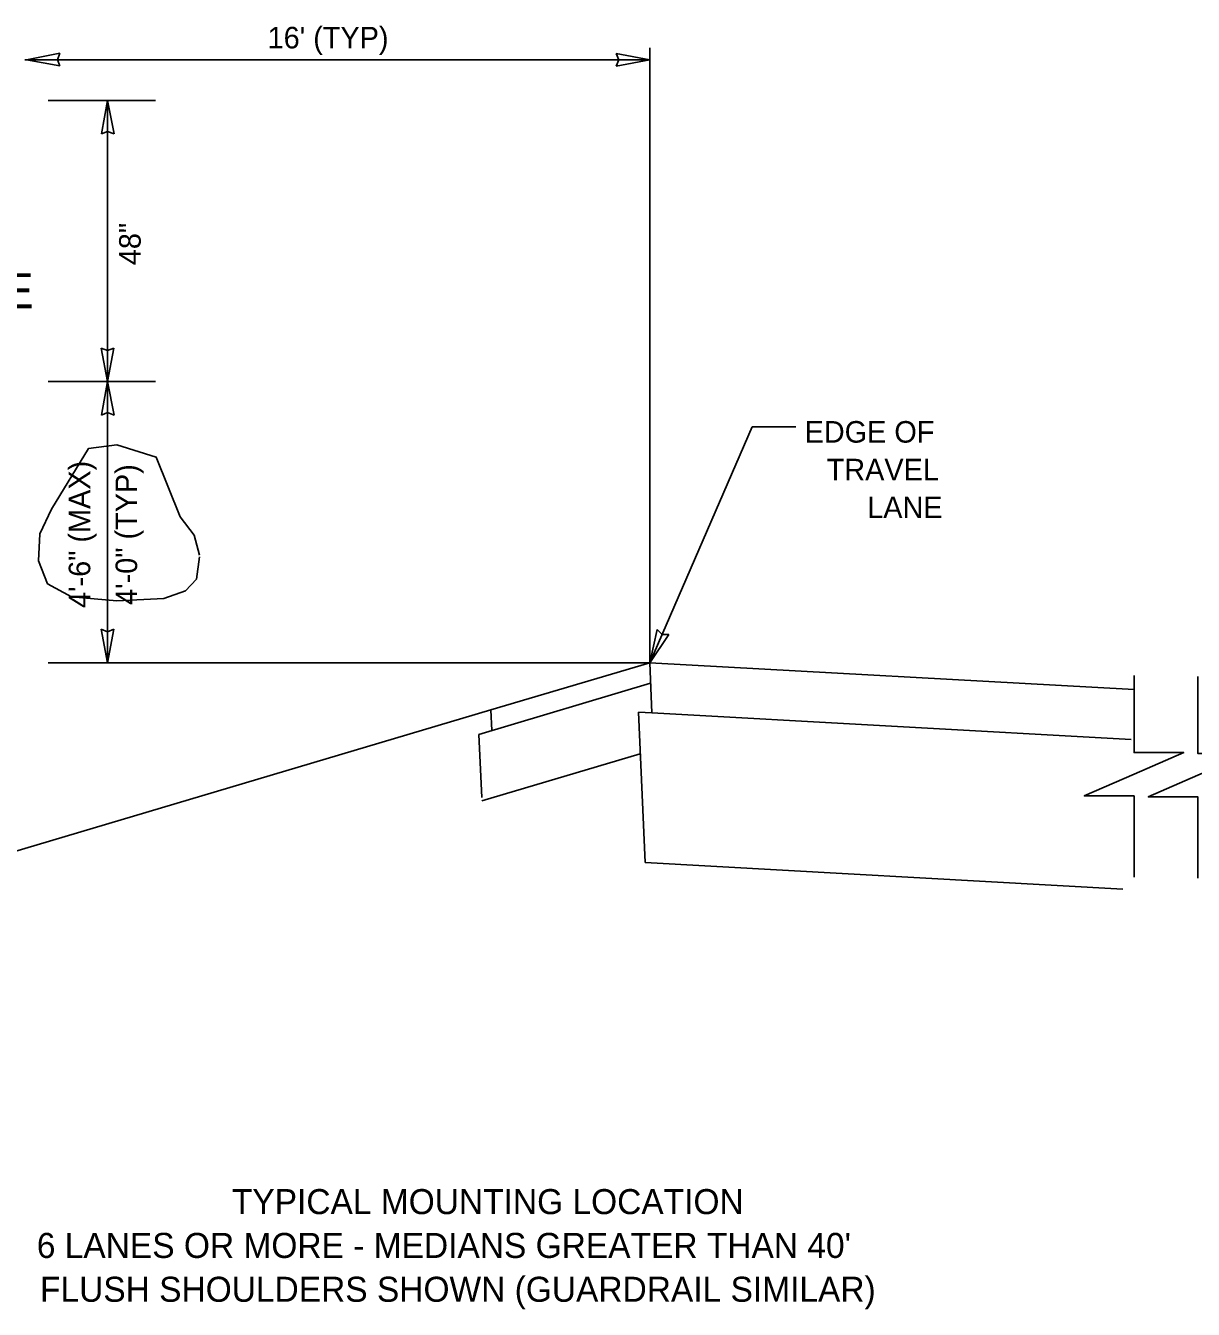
# Model space of a CAD drawing. Extents: x 56768 to 57406, y 11696 to 12105.
# Drawn here: x 57035.7 to 57187.3, y 11742.3 to 11908.9 of the extents above; entities that cross this region are included whole.
import ezdxf

# ---------------------------------------------------------------- set-up
doc = ezdxf.new("R2010")
doc.units = 0
for name, color, linetype in [('52', 7, 'Continuous'), ('62', 7, 'Continuous'), ('Default', 7, 'Continuous'), ('DimLines_dp', 7, 'Continuous'), ('SignPanel', 7, 'Continuous'), ('TextTables', 7, 'Continuous'), ('XSGrdLine_ex', 7, 'Continuous')]:
    doc.layers.add(name, color=color, linetype=linetype)

msp = doc.modelspace()

# ---------------------------------------------------------------- linework, layer by layer
at = {"layer": '52'}
msp.add_line((57038.58, 11826.22), (57116.7, 11826.22), dxfattribs=at)
at = {"layer": '62'}
msp.add_lwpolyline([(57058.24, 11840.16), (57057.54, 11842.76), (57055.73, 11845.17), (57052.63, 11852.92), (57047.53, 11854.52), (57043.83, 11854.02), (57039.03, 11846.17), (57037.53, 11842.96), (57037.33, 11839.46), (57038.53, 11836.46), (57041.63, 11834.75), (57047.53, 11834.25), (57053.63, 11834.55), (57056.43, 11835.56), (57057.84, 11837.06), (57058.24, 11839.96)], dxfattribs=at)
at = {"layer": 'Default'}
for points in [[(57179.58, 11798.37), (57179.58, 11808.93), (57173.12, 11808.93), (57179.58, 11811.74), (57186.04, 11814.56), (57179.58, 11814.56), (57179.58, 11824.56)], [(57187.88, 11798.24), (57187.88, 11808.8), (57181.42, 11808.8), (57187.88, 11811.61), (57194.34, 11814.43), (57187.88, 11814.43), (57187.88, 11824.43)]]:
    msp.add_lwpolyline(points, dxfattribs=at)
at = {"layer": 'DimLines_dp'}
for p, q in [((57116.7, 11826.22), (57116.7, 11906.05)), ((57035.58, 11904.5), (57116.7, 11904.5)), ((57035.77, 11904.5), (57040.12, 11905.34)), ((57040.12, 11903.69), (57035.77, 11904.5)), ((57040.12, 11905.34), (57039.79, 11904.5)), ((57039.79, 11904.5), (57040.12, 11903.69)), ((57112.68, 11904.5), (57112.35, 11905.31)), ((57112.35, 11905.31), (57116.7, 11904.5)), ((57116.7, 11904.5), (57112.35, 11903.66)), ((57112.35, 11903.66), (57112.68, 11904.5)), ((57038.58, 11899.22), (57052.51, 11899.22)), ((57045.51, 11894.87), (57046.32, 11899.22)), ((57046.32, 11899.22), (57046.32, 11862.72)), ((57046.32, 11899.22), (57047.16, 11894.87)), ((57046.32, 11895.2), (57045.51, 11894.87)), ((57047.16, 11894.87), (57046.32, 11895.2)), ((57046.32, 11862.72), (57045.48, 11867.07)), ((57045.48, 11867.07), (57046.32, 11866.74)), ((57046.32, 11862.72), (57045.48, 11867.07)), ((57045.48, 11867.07), (57046.32, 11866.74)), ((57046.32, 11866.74), (57047.13, 11867.07)), ((57047.13, 11867.07), (57046.32, 11862.72)), ((57046.32, 11866.74), (57047.13, 11867.07)), ((57047.13, 11867.07), (57046.32, 11862.72)), ((57038.58, 11862.72), (57052.51, 11862.72)), ((57045.51, 11858.37), (57046.32, 11862.72)), ((57046.32, 11862.72), (57046.32, 11826.22)), ((57046.32, 11862.72), (57047.16, 11858.37)), ((57046.32, 11858.7), (57045.51, 11858.37)), ((57047.16, 11858.37), (57046.32, 11858.7)), ((57130.02, 11856.83), (57116.7, 11826.22)), ((57135.67, 11856.83), (57130.02, 11856.83)), ((57046.32, 11826.22), (57045.48, 11830.57)), ((57045.48, 11830.57), (57046.32, 11830.24)), ((57046.32, 11830.24), (57047.13, 11830.57)), ((57047.13, 11830.57), (57046.32, 11826.22)), ((57116.7, 11826.22), (57117.67, 11830.54)), ((57119.18, 11829.88), (57116.7, 11826.22)), ((57117.67, 11830.54), (57118.31, 11829.9)), ((57118.31, 11829.9), (57119.18, 11829.88))]:
    msp.add_line(p, q, dxfattribs=at)
at = {"layer": 'XSGrdLine_ex'}
for p, q in [((57116.7, 11826.22), (57096.06, 11820.09)), ((57116.99, 11819.71), (57116.7, 11826.22)), ((57116.7, 11826.22), (57179.58, 11822.74)), ((57116.82, 11823.55), (57094.53, 11816.92)), ((57031.1, 11800.77), (57096.06, 11820.09)), ((57096.06, 11820.09), (57096.18, 11817.42)), ((57115.24, 11819.8), (57116.99, 11819.71)), ((57116.11, 11800.26), (57115.24, 11819.8)), ((57179.22, 11816.26), (57116.99, 11819.71)), ((57094.53, 11816.92), (57094.9, 11808.7)), ((57115.48, 11814.4), (57094.91, 11808.28)), ((57116.11, 11800.26), (57178.15, 11796.82))]:
    msp.add_line(p, q, dxfattribs=at)

# ---------------------------------------------------------------- texts
at = {"layer": 'DimLines_dp'}
for s, p in [("16' (TYP)", (57067.09, 11905.97)), ('EDGE OF ', (57136.81, 11854.79)), ('TRAVEL ', (57139.68, 11849.89)), ('LANE', (57144.94, 11844.99))]:
    msp.add_text(s, height=2.8, dxfattribs=at).set_placement(p)
for s, p in [('48"', (57050.61, 11877.83)), ('4\'-6" (MAX)', (57044.06, 11833.32)), ('4\'-0" (TYP)', (57050.15, 11833.72))]:
    msp.add_text(s, height=2.8, rotation=90, dxfattribs=at).set_placement(p)
at = {"layer": 'SignPanel'}
msp.add_text('MILE', height=4.562, dxfattribs=at).set_placement((57022.48, 11872.22))
at = {"layer": 'TextTables'}
for s, p in [('TYPICAL MOUNTING LOCATION', (57062.45, 11754.63)), ("6 LANES OR MORE - MEDIANS GREATER THAN 40'", (57037.12, 11748.94)), ('FLUSH SHOULDERS SHOWN (GUARDRAIL SIMILAR)', (57037.54, 11743.25))]:
    msp.add_text(s, height=3.2524, dxfattribs=at).set_placement(p)

doc.saveas('drawing.dxf')
